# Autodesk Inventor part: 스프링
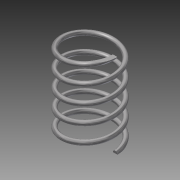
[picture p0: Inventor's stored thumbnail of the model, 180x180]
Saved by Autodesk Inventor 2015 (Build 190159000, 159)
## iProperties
Created: 2016-01
Part Number: 스프링
Material: 스테인레스 스틸
Document SubType Name: Modeling
Designer: 601-23
Density: 8 g/cm^3
Appearance: 반연마
Mass: 8.58443 g
Surface Area: 21.7229 cm^2
Volume: 1.07305 cm^3
Author: 601-23
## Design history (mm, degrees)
sketch "스케치1"
  geometry: L1 (0, 0)-(11, 0); L2 (11, 0)-(11, 37); L3 (11, 37)-(0, 37); L4 (0, 37)-(0, 0); C1 r 1 at (11, 0)
  constraints: 8 end point, 2 parallel, 1 centre point, 1 coincident, 1 horizontal, 1 perpendicular
  dimensions: "d0" = 37 distance of L1.end L2.end (derived); "d1" = 22 diameter of L2 L4; "d2" = 2 diameter of C1
feature "코일1" sketch "스케치1" pitch "d3" = 5; turns "d5" = 5; dims "d4" = 37 (= d0), "d6" = 0, angle "d7" = 90 deg, angle "d8" = 90 deg, "d9" = 0, "d10" = 0
node "작업 평면1"
node "작업 평면2"
sketch "스케치2"
  geometry: L1 (1, 0)-(-1, 0) reference; 1 further point
  constraints: 1 horizontal alignment
extrude "돌출1" cut sketch "스케치2" stored distance "d13" = 10; taper "d14" = 0 deg
sketch "스케치3"
  geometry: L1 (10, 0)-(12, 0) reference; 1 further point
  constraints: 1 horizontal alignment
extrude "돌출2" cut sketch "스케치3" stored distance "d15" = 10; taper "d16" = 0 deg
node "솔리드1"
node "절단 모서리 투영1"
node "절단 모서리 투영2"
other parameters: "d11" = 90 deg, "d12" = 90 deg
